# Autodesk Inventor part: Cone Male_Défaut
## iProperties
Shininess: 64.0
Length Units: 11269
Angle Units: 11279
Time Units: 11290
Mass Units: 11283
Length Display Precision: 3
Angle Display Precision: 2
Compacted: True
Part Number: Cone Male_Défaut
Document SubType Name: Modeling
Created: 2006-11
Material: Par défaut
Designer: profs_sti
Density: 0.0
Volumn: 0.0
Area: 0.0
PropertySet Name: Model Information
Control State: 0
Master: False
Checked Out: False
Author: profs_sti
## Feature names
1. Base1
